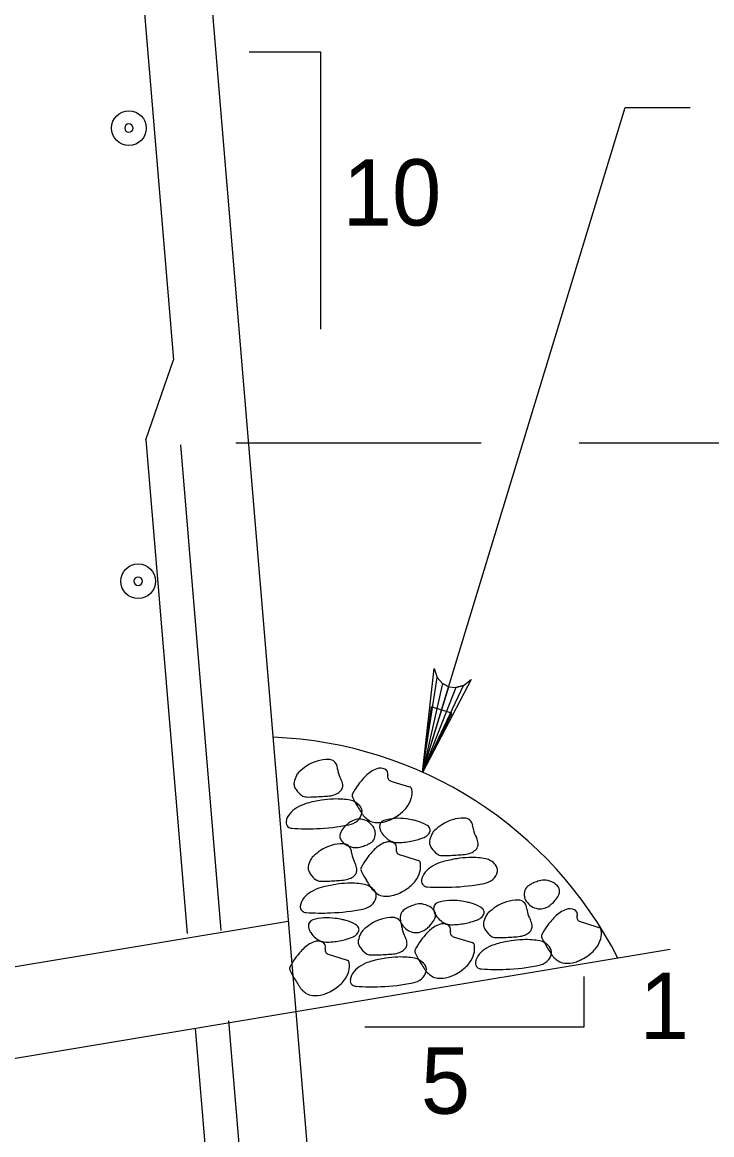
# Model space of a CAD drawing. Extents: x 638255 to 640306, y 296059 to 298435.
# Drawn here: x 639132.2 to 639163.4, y 297062.2 to 297112.6 of the extents above; entities that cross this region are included whole.
import ezdxf

# ---------------------------------------------------------------- set-up
doc = ezdxf.new("R2010")
doc.units = 0
for name, color, linetype in [('3', 7, 'Continuous'), ('Level 3', 7, 'Continuous'), ('Level 5', 7, 'Continuous'), ('Level 8', 7, 'Continuous'), ('Level 9', 7, 'Continuous')]:
    doc.layers.add(name, color=color, linetype=linetype)

# ---------------------------------------------------------------- blocks, each defined once
blk = doc.blocks.new('B')
at = {"layer": '3'}
blk.add_circle((0, 0), 0.16, dxfattribs=at)
for start, end in [(0, 180), (180, 0)]:
    blk.add_arc((0, 0), 0.0391, start, end, dxfattribs=at)

msp = doc.modelspace()

# ---------------------------------------------------------------- linework, layer by layer
at = {"layer": 'Level 3'}
for p, q in [((639150.298, 297078.608), (639159.468, 297108.707)), ((639159.468, 297108.707), (639162.414, 297108.707)), ((639141.842, 297093.526), (639152.942, 297093.526)), ((639157.389, 297093.526), (639193.919, 297093.526))]:
    msp.add_line(p, q, dxfattribs=at)
for points in [[(639150.298, 297078.608), (639150.82, 297083.312), (639150.953, 297082.896), (639151.196, 297082.63), (639151.479, 297082.486), (639151.793, 297082.447), (639152.146, 297082.534), (639152.487, 297082.805), (639150.298, 297078.608), (639152.146, 297082.534), (639151.793, 297082.447), (639150.298, 297078.608), (639151.479, 297082.486), (639151.196, 297082.63), (639150.298, 297078.608), (639150.953, 297082.896)], [(639157.588, 297069.368), (639157.588, 297067.064), (639147.684, 297067.064)]]:
    msp.add_lwpolyline(points, dxfattribs=at)
msp.add_lwpolyline([(639151.626, 297081.285), (639150.687, 297081.569), (639150.298, 297078.608)], close=True, dxfattribs=at)
at = {"layer": 'Level 5'}
for p, q in [((639135.412, 297140.482), (639139.011, 297097.285)), ((639137.772, 297093.669), (639139.011, 297097.285)), ((639137.772, 297093.669), (639139.635, 297071.312)), ((639139.331, 297093.436), (639141.165, 297071.441)), ((639139.995, 297067.008), (639143.538, 297024.483)), ((639141.506, 297067.349), (639146.655, 297005.577))]:
    msp.add_line(p, q, dxfattribs=at)
at = {"layer": 'Level 8'}
for points in [[(639148.851, 297078.215), (639149.094, 297078.138), (639149.703, 297077.947)], [(639149.241, 297074.884), (639149.485, 297074.807), (639150.096, 297074.614)], [(639157.426, 297071.848), (639157.671, 297071.771), (639158.28, 297071.578)], [(639151.685, 297071.166), (639151.93, 297071.089), (639152.539, 297070.896)], [(639146.018, 297070.38), (639146.264, 297070.303), (639146.873, 297070.11)]]:
    msp.add_lwpolyline(points, dxfattribs=at)
for centre, radius, start, end in [((639146.033, 297077.417), 1.773, 89.5772, 124.1443), ((639146.043, 297078.796), 0.394, 11.4529, 89.5772), ((639145.037, 297078.239), 0.506, 132.7374, 153.538), ((639146.687, 297076.453), 2.938, 124.1443, 132.7374), ((639145.11, 297078.607), 1.346, 6.1004, 11.4529), ((639147.349, 297078.846), 0.905, 186.1004, 192.6291), ((639147.764, 297078.939), 1.331, 192.6291, 208.6753), ((639148.654, 297077.549), 1.296, 109.6635, 136.4562), ((639148.387, 297078.296), 0.502, 65.9597, 109.6635), ((639148.497, 297078.544), 0.231, 342.3569, 65.9597), ((639144.779, 297078.087), 0.31, 168.4897, 199.1639), ((639145.731, 297077.894), 1.281, 153.538, 168.4897), ((639145.988, 297077.967), 0.694, 6.391, 28.6753), ((639146.336, 297078.006), 0.344, 338.0834, 6.391), ((639150.17, 297076.018), 3.451, 144.1424, 152.1777), ((639149.639, 297076.402), 2.796, 139.6491, 144.1424), ((639151.727, 297074.628), 5.536, 136.4562, 139.6491), ((639148.912, 297078.412), 0.205, 162.3569, 252.4715), ((639145.008, 297078.167), 0.553, 199.1639, 207.4728), ((639145.301, 297078.319), 0.882, 207.4728, 214.0468), ((639145.443, 297078.415), 1.054, 214.0468, 234.0353), ((639145.039, 297077.859), 0.366, 234.0353, 268.2715), ((639144.889, 297090.409), 12.921, 273.846, 275.2114), ((639145.97, 297078.554), 1.017, 275.2114, 291.5731), ((639146.078, 297078.282), 0.724, 291.5731, 310.9894), ((639146.307, 297078.018), 0.375, 310.9894, 338.0834), ((639147.238, 297077.565), 0.136, 152.1777, 193.5774), ((639147.574, 297077.647), 0.482, 193.5774, 207.4728), ((639149.66, 297077.806), 0.148, 9.0416, 72.4715), ((639148.881, 297077.682), 0.937, 344.9373, 9.0416), ((639145.538, 297075.466), 1.805, 104.9239, 120.8473), ((639145.129, 297080.856), 3.365, 268.2715, 270.9097), ((639146.74, 297070.956), 6.473, 99.0416, 104.9239), ((639145.044, 297086.219), 8.729, 270.9097, 272.5478), ((639144.797, 297091.778), 14.293, 272.5478, 273.846), ((639146.392, 297073.142), 4.259, 91.7881, 99.0416), ((639146.39, 297073.206), 4.195, 86.0442, 91.7881), ((639146.486, 297074.59), 2.807, 79.021, 86.0442), ((639146.888, 297076.662), 0.697, 58.4341, 79.021), ((639152.895, 297080.413), 6.478, 207.4728, 211.2525), ((639146.771, 297076.473), 0.919, 40.5338, 58.4341), ((639162.156, 297086.034), 17.312, 211.2525, 212.2356), ((639147.192, 297076.833), 0.365, 349.0625, 40.5338), ((639148.203, 297078.112), 1.752, 303.0692, 321.7572), ((639148.68, 297077.736), 1.144, 321.7572, 344.9373), ((639144.817, 297076.272), 0.71, 139.2037, 172.3458), ((639145.31, 297075.847), 1.361, 120.8473, 139.2037), ((639146.958, 297076.878), 0.603, 309.5539, 349.0625), ((639150.702, 297078.811), 3.77, 212.2356, 214.3424), ((639148.063, 297077.007), 0.574, 214.3424, 227.6953), ((639148.868, 297077.892), 1.77, 227.6953, 235.2847), ((639149.214, 297074.204), 2.322, 81.3134, 106.8084), ((639147.653, 297078.956), 2.759, 295.7443, 303.0692), ((639152.166, 297074.767), 1.773, 89.5772, 124.1443), ((639152.176, 297076.145), 0.394, 11.4529, 89.5772), ((639144.358, 297076.334), 0.246, 172.3458, 230.2635), ((639144.399, 297076.384), 0.312, 230.2635, 266.2346), ((639145.058, 297086.386), 10.335, 266.2346, 272.3841), ((639145.069, 297086.11), 10.059, 272.3841, 280.7777), ((639147.722, 297075.265), 1.297, 136.4654, 149.2422), ((639147.718, 297075.268), 1.292, 117.4803, 136.4654), ((639146.787, 297077.085), 0.872, 280.7777, 309.5539), ((639147.44, 297075.803), 0.689, 91.376, 117.4803), ((639147.44, 297075.813), 0.68, 65.3457, 91.376), ((639147.398, 297075.722), 0.779, 41.057, 65.3457), ((639148.184, 297076.904), 0.568, 235.2847, 266.0442), ((639147.301, 297075.637), 0.909, 27.4728, 41.057), ((639147.711, 297075.851), 0.446, 8.0357, 27.4728), ((639148.243, 297077.769), 1.436, 266.0442, 285.2565), ((639148.622, 297076.164), 0.275, 106.8084, 186.6218), ((639148.929, 297076.2), 0.584, 186.6218, 200.3491), ((639148.266, 297077.685), 1.348, 285.2565, 295.7443), ((639148.636, 297070.42), 6.15, 78.4814, 81.3134), ((639149.409, 297074.214), 2.278, 73.8272, 78.4814), ((639149.45, 297074.356), 2.13, 61.1605, 73.8272), ((639150.306, 297075.91), 0.356, 29.8544, 61.1605), ((639150.456, 297075.996), 0.183, 347.2445, 29.8544), ((639152.819, 297073.802), 2.938, 124.1443, 132.7374), ((639151.242, 297075.956), 1.346, 6.1004, 11.4529), ((639153.481, 297076.196), 0.905, 186.1004, 192.6291), ((639146.889, 297075.727), 0.339, 171.9761, 209.5935), ((639146.963, 297075.717), 0.414, 149.2422, 171.9761), ((639147.115, 297075.855), 0.599, 209.5935, 237.6667), ((639147.742, 297075.766), 0.403, 299.831, 337.0418), ((639147.584, 297075.833), 0.575, 337.0418, 8.0357), ((639149.047, 297076.244), 0.71, 200.3491, 212.797), ((639149.371, 297076.452), 1.095, 212.797, 230.2213), ((639149.186, 297076.23), 0.806, 230.2213, 250.5601), ((639149.199, 297078.547), 3.113, 281.8686, 292.039), ((639150.183, 297076.116), 0.49, 292.039, 317.8475), ((639150.268, 297076.039), 0.375, 317.8475, 347.2445), ((639151.863, 297075.243), 1.281, 153.538, 168.4897), ((639151.169, 297075.589), 0.506, 132.7374, 153.538), ((639153.897, 297076.289), 1.331, 192.6291, 208.6753), ((639152.12, 297075.317), 0.694, 6.391, 28.6753), ((639147.329, 297072.639), 2.938, 124.1443, 132.7374), ((639146.675, 297073.603), 1.773, 89.5772, 124.1443), ((639146.685, 297074.982), 0.394, 11.4529, 89.5772), ((639147.341, 297076.213), 1.022, 237.6667, 259.0544), ((639145.752, 297074.793), 1.346, 6.1004, 11.4529), ((639147.273, 297075.857), 0.66, 259.0544, 285.7584), ((639146.148, 297079.842), 4.8, 285.7584, 288.5059), ((639147.272, 297076.485), 1.26, 288.5059, 293.8705), ((639147.323, 297076.369), 1.133, 293.8705, 297.4803), ((639146.614, 297077.733), 2.671, 297.4803, 299.831), ((639152.119, 297071.296), 5.536, 136.4562, 139.6491), ((639149.046, 297074.216), 1.296, 109.6635, 136.4562), ((639148.778, 297074.964), 0.502, 65.9597, 109.6635), ((639149.184, 297076.224), 0.8, 250.5601, 271.915), ((639148.889, 297075.212), 0.231, 342.3569, 65.9597), ((639149.304, 297075.08), 0.205, 162.3569, 252.4715), ((639149.089, 297079.072), 3.65, 271.915, 281.8686), ((639150.911, 297075.437), 0.31, 168.4897, 199.1639), ((639151.141, 297075.517), 0.553, 199.1639, 207.4728), ((639151.433, 297075.669), 0.882, 207.4728, 214.0468), ((639151.575, 297075.764), 1.054, 214.0468, 234.0353), ((639152.21, 297075.631), 0.724, 291.5731, 310.9894), ((639152.44, 297075.367), 0.375, 310.9894, 338.0834), ((639152.468, 297075.356), 0.344, 338.0834, 6.391), ((639146.373, 297074.08), 1.281, 153.538, 168.4897), ((639145.679, 297074.425), 0.506, 132.7374, 153.538), ((639147.991, 297075.032), 0.905, 186.1004, 192.6291), ((639148.406, 297075.125), 1.331, 192.6291, 208.6753), ((639150.562, 297072.686), 3.451, 144.1424, 152.1777), ((639150.031, 297073.07), 2.796, 139.6491, 144.1424), ((639150.052, 297074.474), 0.148, 9.0416, 72.4715), ((639151.67, 297072.815), 1.805, 104.9239, 120.8473), ((639151.171, 297075.208), 0.366, 234.0353, 268.2715), ((639151.262, 297078.206), 3.365, 268.2715, 270.9097), ((639152.872, 297068.305), 6.473, 99.0416, 104.9239), ((639151.177, 297083.569), 8.729, 270.9097, 272.5478), ((639150.929, 297089.127), 14.293, 272.5478, 273.846), ((639152.524, 297070.492), 4.259, 91.7881, 99.0416), ((639151.021, 297087.759), 12.921, 273.846, 275.2114), ((639152.103, 297075.904), 1.017, 275.2114, 291.5731), ((639152.522, 297070.555), 4.195, 86.0442, 91.7881), ((639152.618, 297071.94), 2.807, 79.021, 86.0442), ((639153.02, 297074.012), 0.697, 58.4341, 79.021), ((639152.904, 297073.822), 0.919, 40.5338, 58.4341), ((639145.421, 297074.274), 0.31, 168.4897, 199.1639), ((639145.65, 297074.353), 0.553, 199.1639, 207.4728), ((639145.943, 297074.505), 0.882, 207.4728, 214.0468), ((639146.085, 297074.601), 1.054, 214.0468, 234.0353), ((639146.949, 297074.204), 0.375, 310.9894, 338.0834), ((639146.629, 297074.154), 0.694, 6.391, 28.6753), ((639146.978, 297074.193), 0.344, 338.0834, 6.391), ((639147.63, 297074.233), 0.136, 152.1777, 193.5774), ((639147.966, 297074.314), 0.482, 193.5774, 207.4728), ((639153.287, 297077.081), 6.478, 207.4728, 211.2525), ((639149.072, 297074.404), 1.144, 321.7572, 344.9373), ((639149.272, 297074.35), 0.937, 344.9373, 9.0416), ((639150.95, 297073.622), 0.71, 139.2037, 172.3458), ((639151.442, 297073.196), 1.361, 120.8473, 139.2037), ((639153.091, 297074.227), 0.603, 309.5539, 349.0625), ((639153.324, 297074.182), 0.365, 349.0625, 40.5338), ((639145.681, 297074.045), 0.366, 234.0353, 268.2715), ((639145.771, 297077.042), 3.365, 268.2715, 270.9097), ((639147.382, 297067.142), 6.473, 99.0416, 104.9239), ((639145.686, 297082.405), 8.729, 270.9097, 272.5478), ((639145.439, 297087.964), 14.293, 272.5478, 273.846), ((639147.034, 297069.328), 4.259, 91.7881, 99.0416), ((639145.531, 297086.595), 12.921, 273.846, 275.2114), ((639146.612, 297074.74), 1.017, 275.2114, 291.5731), ((639147.032, 297069.392), 4.195, 86.0442, 91.7881), ((639146.72, 297074.468), 0.724, 291.5731, 310.9894), ((639147.128, 297070.777), 2.807, 79.021, 86.0442), ((639147.53, 297072.849), 0.697, 58.4341, 79.021), ((639162.548, 297082.701), 17.312, 211.2525, 212.2356), ((639148.594, 297074.78), 1.752, 303.0692, 321.7572), ((639150.49, 297073.683), 0.246, 172.3458, 230.2635), ((639151.201, 297083.459), 10.059, 272.3841, 280.7777), ((639152.919, 297074.435), 0.872, 280.7777, 309.5539), ((639156.542, 297071.235), 2.671, 120.6031, 122.9538), ((639155.759, 297072.558), 1.133, 116.9933, 120.6031), ((639155.817, 297072.445), 1.26, 111.6288, 116.9933), ((639157.122, 297069.154), 4.8, 108.8812, 111.6288), ((639155.782, 297073.071), 0.66, 82.1773, 108.8812), ((639155.733, 297072.713), 1.022, 60.7895, 82.1773), ((639155.939, 297073.082), 0.599, 32.7163, 60.7895), ((639145.952, 297072.033), 1.361, 120.8473, 139.2037), ((639146.18, 297071.652), 1.805, 104.9239, 120.8473), ((639147.413, 297072.659), 0.919, 40.5338, 58.4341), ((639151.094, 297075.478), 3.77, 212.2356, 214.3424), ((639148.454, 297073.675), 0.574, 214.3424, 227.6953), ((639149.26, 297074.56), 1.77, 227.6953, 235.2847), ((639147.834, 297073.019), 0.365, 349.0625, 40.5338), ((639148.575, 297073.572), 0.568, 235.2847, 266.0442), ((639148.635, 297074.437), 1.436, 266.0442, 285.2565), ((639148.658, 297074.353), 1.348, 285.2565, 295.7443), ((639148.045, 297075.624), 2.759, 295.7443, 303.0692), ((639150.532, 297073.734), 0.312, 230.2635, 266.2346), ((639151.19, 297083.736), 10.335, 266.2346, 272.3841), ((639155.47, 297073.079), 0.575, 160.1647, 191.1585), ((639155.309, 297073.138), 0.403, 122.9538, 160.1647), ((639155.301, 297073.639), 1.297, 319.5882, 332.365), ((639156.158, 297073.223), 0.339, 355.0989, 32.7163), ((639156.084, 297073.229), 0.414, 332.365, 355.0989), ((639145, 297072.52), 0.246, 172.3458, 230.2635), ((639145.459, 297072.458), 0.71, 139.2037, 172.3458), ((639147.429, 297073.272), 0.872, 280.7777, 309.5539), ((639147.6, 297073.064), 0.603, 309.5539, 349.0625), ((639150.202, 297071.367), 1.26, 111.6288, 116.9933), ((639151.507, 297068.076), 4.8, 108.8812, 111.6288), ((639150.168, 297071.993), 0.66, 82.1773, 108.8812), ((639150.118, 297071.635), 1.022, 60.7895, 82.1773), ((639150.325, 297072.004), 0.599, 32.7163, 60.7895), ((639151.066, 297072.446), 0.275, 106.8084, 186.6218), ((639151.658, 297070.486), 2.322, 81.3134, 106.8084), ((639151.08, 297066.703), 6.15, 78.4814, 81.3134), ((639151.853, 297070.497), 2.278, 73.8272, 78.4814), ((639151.894, 297070.638), 2.13, 61.1605, 73.8272), ((639152.75, 297072.192), 0.356, 29.8544, 61.1605), ((639155.264, 297070.085), 2.938, 124.1443, 132.7374), ((639154.61, 297071.049), 1.773, 89.5772, 124.1443), ((639154.62, 297072.428), 0.394, 11.4529, 89.5772), ((639155.344, 297073.054), 0.446, 191.1585, 210.5956), ((639155.742, 297073.29), 0.909, 210.5956, 224.1798), ((639153.686, 297072.238), 1.346, 6.1004, 11.4529), ((639155.649, 297073.2), 0.779, 224.1798, 248.4685), ((639155.612, 297073.116), 0.689, 274.4988, 300.6031), ((639155.305, 297073.635), 1.292, 300.6031, 319.5882), ((639145.041, 297072.57), 0.312, 230.2635, 266.2346), ((639145.7, 297082.572), 10.335, 266.2346, 272.3841), ((639145.992, 297069.701), 2.322, 81.3134, 106.8084), ((639145.711, 297082.296), 10.059, 272.3841, 280.7777), ((639145.413, 297065.917), 6.15, 78.4814, 81.3134), ((639148.943, 297070.263), 1.773, 89.5772, 124.1443), ((639148.953, 297071.642), 0.394, 11.4529, 89.5772), ((639149.856, 297072.001), 0.575, 160.1647, 191.1585), ((639149.694, 297072.06), 0.403, 122.9538, 160.1647), ((639150.928, 297070.157), 2.671, 120.6031, 122.9538), ((639150.145, 297071.48), 1.133, 116.9933, 120.6031), ((639151.373, 297072.482), 0.584, 186.6218, 200.3491), ((639151.491, 297072.526), 0.71, 200.3491, 212.797), ((639150.544, 297072.145), 0.339, 355.0989, 32.7163), ((639150.469, 297072.151), 0.414, 332.365, 355.0989), ((639151.815, 297072.734), 1.095, 212.797, 230.2213), ((639152.627, 297072.398), 0.49, 292.039, 317.8475), ((639152.712, 297072.321), 0.375, 317.8475, 347.2445), ((639154.307, 297071.525), 1.281, 153.538, 168.4897), ((639152.9, 297072.279), 0.183, 347.2445, 29.8544), ((639153.613, 297071.871), 0.506, 132.7374, 153.538), ((639155.925, 297072.478), 0.905, 186.1004, 192.6291), ((639156.341, 297072.571), 1.331, 192.6291, 208.6753), ((639155.613, 297073.107), 0.68, 248.4685, 274.4988), ((639160.304, 297068.26), 5.536, 136.4562, 139.6491), ((639157.23, 297071.18), 1.296, 109.6635, 136.4562), ((639156.963, 297071.928), 0.502, 65.9597, 109.6635), ((639157.074, 297072.176), 0.231, 342.3569, 65.9597), ((639157.489, 297072.044), 0.205, 162.3569, 252.4715), ((639145.399, 297071.661), 0.275, 106.8084, 186.6218), ((639145.707, 297071.696), 0.584, 186.6218, 200.3491), ((639145.825, 297071.74), 0.71, 200.3491, 212.797), ((639146.187, 297069.711), 2.278, 73.8272, 78.4814), ((639146.228, 297069.852), 2.13, 61.1605, 73.8272), ((639147.083, 297071.407), 0.356, 29.8544, 61.1605), ((639147.234, 297071.493), 0.183, 347.2445, 29.8544), ((639149.597, 297069.299), 2.938, 124.1443, 132.7374), ((639149.729, 297071.976), 0.446, 191.1585, 210.5956), ((639148.02, 297071.453), 1.346, 6.1004, 11.4529), ((639150.128, 297072.212), 0.909, 210.5956, 224.1798), ((639150.259, 297071.692), 0.905, 186.1004, 192.6291), ((639150.674, 297071.785), 1.331, 192.6291, 208.6753), ((639150.035, 297072.121), 0.779, 224.1798, 248.4685), ((639149.69, 297072.557), 1.292, 300.6031, 319.5882), ((639151.49, 297070.499), 1.296, 109.6635, 136.4562), ((639149.686, 297072.561), 1.297, 319.5882, 332.365), ((639151.223, 297071.246), 0.502, 65.9597, 109.6635), ((639151.63, 297072.512), 0.806, 230.2213, 250.5601), ((639151.628, 297072.507), 0.8, 250.5601, 271.915), ((639151.333, 297071.494), 0.231, 342.3569, 65.9597), ((639151.533, 297075.355), 3.65, 271.915, 281.8686), ((639151.643, 297074.829), 3.113, 281.8686, 292.039), ((639153.355, 297071.719), 0.31, 168.4897, 199.1639), ((639153.585, 297071.799), 0.553, 199.1639, 207.4728), ((639153.877, 297071.951), 0.882, 207.4728, 214.0468), ((639154.884, 297071.65), 0.375, 310.9894, 338.0834), ((639154.564, 297071.599), 0.694, 6.391, 28.6753), ((639154.912, 297071.638), 0.344, 338.0834, 6.391), ((639158.746, 297069.65), 3.451, 144.1424, 152.1777), ((639158.216, 297070.034), 2.796, 139.6491, 144.1424), ((639158.236, 297071.438), 0.148, 9.0416, 72.4715), ((639146.149, 297071.949), 1.095, 212.797, 230.2213), ((639145.964, 297071.726), 0.806, 230.2213, 250.5601), ((639145.866, 297074.569), 3.65, 271.915, 281.8686), ((639145.977, 297074.043), 3.113, 281.8686, 292.039), ((639146.961, 297071.613), 0.49, 292.039, 317.8475), ((639147.046, 297071.535), 0.375, 317.8475, 347.2445), ((639147.689, 297070.933), 0.31, 168.4897, 199.1639), ((639148.641, 297070.739), 1.281, 153.538, 168.4897), ((639147.947, 297071.085), 0.506, 132.7374, 153.538), ((639148.898, 297070.813), 0.694, 6.391, 28.6753), ((639149.998, 297072.029), 0.68, 248.4685, 274.4988), ((639153.006, 297068.968), 3.451, 144.1424, 152.1777), ((639149.997, 297072.038), 0.689, 274.4988, 300.6031), ((639152.475, 297069.352), 2.796, 139.6491, 144.1424), ((639154.563, 297067.578), 5.536, 136.4562, 139.6491), ((639151.748, 297071.362), 0.205, 162.3569, 252.4715), ((639154.019, 297072.047), 1.054, 214.0468, 234.0353), ((639153.615, 297071.49), 0.366, 234.0353, 268.2715), ((639153.706, 297074.488), 3.365, 268.2715, 270.9097), ((639153.621, 297079.851), 8.729, 270.9097, 272.5478), ((639153.373, 297085.409), 14.293, 272.5478, 273.846), ((639154.968, 297066.774), 4.259, 91.7881, 99.0416), ((639153.465, 297084.041), 12.921, 273.846, 275.2114), ((639154.547, 297072.186), 1.017, 275.2114, 291.5731), ((639154.966, 297066.838), 4.195, 86.0442, 91.7881), ((639154.654, 297071.914), 0.724, 291.5731, 310.9894), ((639155.062, 297068.222), 2.807, 79.021, 86.0442), ((639155.814, 297071.197), 0.136, 152.1777, 193.5774), ((639156.151, 297071.278), 0.482, 193.5774, 207.4728), ((639161.471, 297074.045), 6.478, 207.4728, 211.2525), ((639157.257, 297071.368), 1.144, 321.7572, 344.9373), ((639157.457, 297071.314), 0.937, 344.9373, 9.0416), ((639148.897, 297066.792), 5.536, 136.4562, 139.6491), ((639145.823, 297069.713), 1.296, 109.6635, 136.4562), ((639145.556, 297070.46), 0.502, 65.9597, 109.6635), ((639145.962, 297071.721), 0.8, 250.5601, 271.915), ((639145.667, 297070.708), 0.231, 342.3569, 65.9597), ((639146.082, 297070.576), 0.205, 162.3569, 252.4715), ((639147.918, 297071.013), 0.553, 199.1639, 207.4728), ((639148.211, 297071.165), 0.882, 207.4728, 214.0468), ((639148.353, 297071.261), 1.054, 214.0468, 234.0353), ((639148.988, 297071.128), 0.724, 291.5731, 310.9894), ((639149.217, 297070.864), 0.375, 310.9894, 338.0834), ((639149.246, 297070.852), 0.344, 338.0834, 6.391), ((639150.074, 297070.515), 0.136, 152.1777, 193.5774), ((639150.41, 297070.597), 0.482, 193.5774, 207.4728), ((639152.496, 297070.756), 0.148, 9.0416, 72.4715), ((639151.716, 297070.632), 0.937, 344.9373, 9.0416), ((639153.887, 297069.479), 1.361, 120.8473, 139.2037), ((639154.114, 297069.097), 1.805, 104.9239, 120.8473), ((639155.316, 297064.587), 6.473, 99.0416, 104.9239), ((639155.464, 297070.294), 0.697, 58.4341, 79.021), ((639155.348, 297070.105), 0.919, 40.5338, 58.4341), ((639170.733, 297079.665), 17.312, 211.2525, 212.2356), ((639155.768, 297070.464), 0.365, 349.0625, 40.5338), ((639156.779, 297071.744), 1.752, 303.0692, 321.7572), ((639147.339, 297068.182), 3.451, 144.1424, 152.1777), ((639146.808, 297068.566), 2.796, 139.6491, 144.1424), ((639146.829, 297069.97), 0.148, 9.0416, 72.4715), ((639146.05, 297069.846), 0.937, 344.9373, 9.0416), ((639148.448, 297068.312), 1.805, 104.9239, 120.8473), ((639147.949, 297070.705), 0.366, 234.0353, 268.2715), ((639148.04, 297073.702), 3.365, 268.2715, 270.9097), ((639149.65, 297063.802), 6.473, 99.0416, 104.9239), ((639147.954, 297079.065), 8.729, 270.9097, 272.5478), ((639147.707, 297084.623), 14.293, 272.5478, 273.846), ((639149.302, 297065.988), 4.259, 91.7881, 99.0416), ((639147.799, 297083.255), 12.921, 273.846, 275.2114), ((639148.88, 297071.4), 1.017, 275.2114, 291.5731), ((639149.3, 297066.052), 4.195, 86.0442, 91.7881), ((639149.396, 297067.436), 2.807, 79.021, 86.0442), ((639149.798, 297069.508), 0.697, 58.4341, 79.021), ((639155.731, 297073.363), 6.478, 207.4728, 211.2525), ((639149.681, 297069.319), 0.919, 40.5338, 58.4341), ((639164.992, 297078.984), 17.312, 211.2525, 212.2356), ((639151.038, 297071.062), 1.752, 303.0692, 321.7572), ((639151.516, 297070.686), 1.144, 321.7572, 344.9373), ((639152.934, 297069.966), 0.246, 172.3458, 230.2635), ((639153.394, 297069.904), 0.71, 139.2037, 172.3458), ((639155.363, 297070.717), 0.872, 280.7777, 309.5539), ((639155.535, 297070.509), 0.603, 309.5539, 349.0625), ((639159.279, 297072.442), 3.77, 212.2356, 214.3424), ((639156.639, 297070.639), 0.574, 214.3424, 227.6953), ((639157.444, 297071.524), 1.77, 227.6953, 235.2847), ((639156.76, 297070.536), 0.568, 235.2847, 266.0442), ((639156.82, 297071.401), 1.436, 266.0442, 285.2565), ((639156.843, 297071.317), 1.348, 285.2565, 295.7443), ((639156.23, 297072.588), 2.759, 295.7443, 303.0692), ((639144.407, 297069.73), 0.136, 152.1777, 193.5774), ((639144.744, 297069.811), 0.482, 193.5774, 207.4728), ((639150.064, 297072.577), 6.478, 207.4728, 211.2525), ((639145.85, 297069.9), 1.144, 321.7572, 344.9373), ((639147.727, 297069.118), 0.71, 139.2037, 172.3458), ((639148.22, 297068.693), 1.361, 120.8473, 139.2037), ((639149.869, 297069.724), 0.603, 309.5539, 349.0625), ((639153.538, 297071.761), 3.77, 212.2356, 214.3424), ((639150.102, 297069.679), 0.365, 349.0625, 40.5338), ((639150.898, 297069.957), 0.574, 214.3424, 227.6953), ((639151.704, 297070.842), 1.77, 227.6953, 235.2847), ((639150.489, 297071.906), 2.759, 295.7443, 303.0692), ((639152.976, 297070.016), 0.312, 230.2635, 266.2346), ((639153.634, 297080.018), 10.335, 266.2346, 272.3841), ((639153.646, 297079.741), 10.059, 272.3841, 280.7777), ((639159.326, 297078.198), 17.312, 211.2525, 212.2356), ((639145.372, 297070.276), 1.752, 303.0692, 321.7572), ((639147.268, 297069.18), 0.246, 172.3458, 230.2635), ((639147.309, 297069.23), 0.312, 230.2635, 266.2346), ((639147.979, 297078.955), 10.059, 272.3841, 280.7777), ((639149.697, 297069.931), 0.872, 280.7777, 309.5539), ((639151.019, 297069.854), 0.568, 235.2847, 266.0442), ((639151.079, 297070.719), 1.436, 266.0442, 285.2565), ((639151.102, 297070.635), 1.348, 285.2565, 295.7443), ((639147.872, 297070.975), 3.77, 212.2356, 214.3424), ((639145.232, 297069.171), 0.574, 214.3424, 227.6953), ((639146.037, 297070.056), 1.77, 227.6953, 235.2847), ((639145.353, 297069.068), 0.568, 235.2847, 266.0442), ((639145.413, 297069.934), 1.436, 266.0442, 285.2565), ((639145.436, 297069.849), 1.348, 285.2565, 295.7443), ((639144.823, 297071.12), 2.759, 295.7443, 303.0692), ((639147.968, 297079.232), 10.335, 266.2346, 272.3841)]:
    msp.add_arc(centre, radius, start, end, dxfattribs=at)
at = {"layer": 'Level 9'}
for p, q in [((639136.89, 297159.704), (639148.287, 297022.948)), ((639144.211, 297071.859), (639118.471, 297067.569)), ((639161.503, 297070.592), (639118.471, 297063.421))]:
    msp.add_line(p, q, dxfattribs=at)
msp.add_lwpolyline([(639142.442, 297111.227), (639145.667, 297111.227), (639145.667, 297098.668)], dxfattribs=at)
msp.add_arc((639142.819, 297061.911), 18.297, 26.9324, 87.7453, dxfattribs=at)

# ---------------------------------------------------------------- block references
at = {"layer": 'Level 3', "xscale": 4.911876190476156, "yscale": 4.911876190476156, "rotation": 90}
for p in [(639137.002, 297107.779), (639137.422, 297087.259)]:
    msp.add_blockref('B', p, dxfattribs=at)

# ---------------------------------------------------------------- texts
at = {"layer": 'Level 3'}
for s, height, p in [('10', 3.0001, (639146.68, 297103.368)), ('1', 3, (639160.121, 297066.532)), ('5', 3, (639150.217, 297063.149))]:
    msp.add_text(s, height=height, dxfattribs=at).set_placement(p)

doc.saveas('drawing.dxf')
